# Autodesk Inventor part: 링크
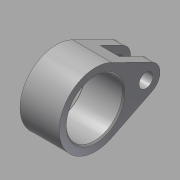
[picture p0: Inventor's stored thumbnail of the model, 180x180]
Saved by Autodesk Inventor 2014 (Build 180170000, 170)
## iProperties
Created: 2016-02
Part Number: 링크
Material: 강철, 연강
Document SubType Name: Modeling
Designer: test
Density: 1 g/cm^3
Appearance: Steel
Author: test
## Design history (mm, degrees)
sketch "스케치1"
  geometry: L1 (20.222, 4.479)-(5.778, 11.645); L2 (20.222, -4.479)-(5.778, -11.645); A1 r 13 centre (0, 0) between (5.778, 11.645) and (5.778, -11.645); A2 r 5 centre (18, 0) between (20.222, -4.479) and (20.222, 4.479); 1 further point
  constraints: 4 end point, 4 point on circle, 4 tangent, 2 centre point, 1 coincident, 1 horizontal alignment
  dimensions: "d0" = 18 distance of point (0, 0) A2.centre; "d1" = 13 radius of A1; "d2" = 5 radius of A2
extrude "돌출1" new body sketch "스케치1" stored distance "d3" = 14; taper "d4" = 0 deg
sketch "스케치2"
  geometry: C1 r 10 at (0, 0); 1 further point
  constraints: 1 centre point, 1 coincident
  dimensions: "d5" = 20 diameter of C1
extrude "돌출2" cut sketch "스케치2" stored distance "d6" = 14; taper "d7" = 0 deg
sketch "스케치3"
  geometry: C1 r 2.5 at (18, 0); A1 r 5 centre (18, 0) between (20.222, -4.479) and (20.222, 4.479) reference; 1 further point
  constraints: 1 centre point, 1 coincident
  dimensions: "d8" = 5 diameter of C1
extrude "돌출3" cut sketch "스케치3" stored distance "d9" = 14; taper "d10" = 0 deg
sketch "스케치4"
  geometry: L1 (20.222, -4.479)-(5.778, -11.645) reference; L2 (5.778, 11.645)-(20.222, 4.479) reference; L3 (12, 8.558)-(12, -8.558); C1 r 2.5 at (18, 0) reference; C2 r 10 at (0, 0) reference; A1 r 13 centre (0, 0) between (5.778, 11.645) and (5.778, -11.645) reference; A2 r 5 centre (18, 0) between (20.222, -4.479) and (20.222, 4.479) reference; 1 further point
  constraints: 2 end point, 2 point on line, 1 vertical
  dimensions: "d11" = 12 distance from line of L3 point (0, 0)
extrude "돌출4" cut sketch "스케치4" stored distance "d12" = 7; taper "d13" = 0 deg
chamfer "모따기1" distance "d14" = 0.5; stored, may be unused: second distance "d15" = 2, angle "d16" = 45 deg
node "솔리드1"
node "절단 모서리 투영1"
